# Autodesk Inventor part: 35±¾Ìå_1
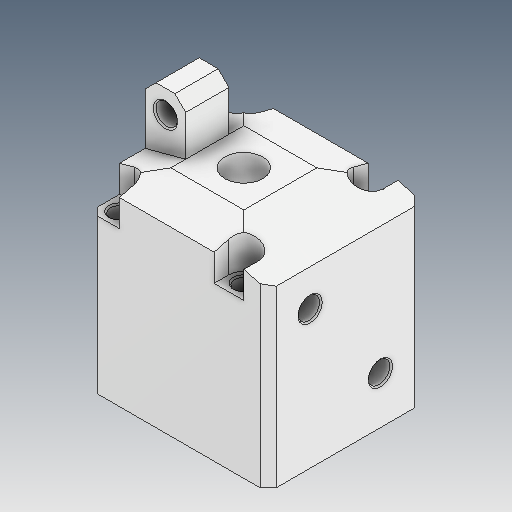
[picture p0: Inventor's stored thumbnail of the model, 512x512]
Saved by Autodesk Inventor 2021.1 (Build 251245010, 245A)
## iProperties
Created: 2021-05
Part Number: 35±¾Ìå_1
Material: Ogólny
Document SubType Name: Modeling
Designer: user
Density: 1 g/cm^3
Appearance: Domyślna
Author: user
Revision Number: ÈÎºÎ
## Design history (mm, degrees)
feature "ÊäÈë1"
node "Bryła1"
